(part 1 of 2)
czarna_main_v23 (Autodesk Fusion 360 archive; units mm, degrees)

design "czarna_main" references "sprzeglo_6,35x8mm", "karetka_plecy", "bok_zetki", "SHF_16", "sruba_TR8x8_180mm", "karetka_dol", "uchwyt_nakretki", "Pet_16mm", "Spindle Holder 65mm", "baza_tyl_front", "SMA_16_UU", "Silnik_krokowy_NEMA23", "gora_karetki", "front_zetki", "SA16_500mm", "nowe_plecy_X", "Blat_glowny", "Limit Switch 2", "Nakretka_TR8x8", "stopka", "Water Cooled Spindle Motor 1", "sruba_TR8x8", "bok_x", "baza_bok", "mocowanie_silnika", "KFL_08", "nasadki_boczne", "SME-L16OP"
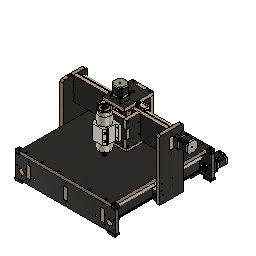
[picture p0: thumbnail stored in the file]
component_insert "Component Insert1"
ground "Ground1"
component_insert "Component Insert2"
component_insert "Component Insert3"
position "Position1"
joint "Assemble2" alignAngle 0 alignOffsetX 0 alignOffsetY 0 alignOffsetZ 0
component_insert "Component Insert4"
joint "Assemble3" alignAngle 0 alignOffsetX 0 alignOffsetY 0 alignOffsetZ 0
component_insert "Component Insert5"
joint "Assemble4" alignAngle 0 alignOffsetX 0 alignOffsetY 0 alignOffsetZ 0
component_insert "Component Insert6"
joint "Assemble5" alignAngle 180 alignOffsetX 0 alignOffsetY 0 alignOffsetZ 0
component_insert "Component Insert7"
joint "Assemble6" alignAngle 0 alignOffsetX 0 alignOffsetY 0 alignOffsetZ 0
component_insert "Component Insert8"
joint "Assemble7" alignAngle -180 alignOffsetX 0 alignOffsetY 0 alignOffsetZ 0
component_insert "Component Insert9"
joint "Assemble8" alignAngle 90 alignOffsetX 0 alignOffsetY 0 alignOffsetZ 0
component_insert "Component Insert10"
joint "Assemble9" alignAngle -90 alignOffsetX 0 alignOffsetY 0 alignOffsetZ 18
component_insert "Component Insert11"
joint "Assemble10" alignAngle 180 alignOffsetX 0 alignOffsetY 0 alignOffsetZ 0
component_insert "Component Insert12"
joint "Assemble11" alignAngle -90 alignOffsetX 0 alignOffsetY 0 alignOffsetZ -28
component_insert "Component Insert13"
joint "Assemble12" alignAngle -90 alignOffsetX 0 alignOffsetY 0 alignOffsetZ 0
component_insert "Component Insert14"
joint "Assemble13" alignAngle -90 alignOffsetX 0 alignOffsetY 9 alignOffsetZ 0
component_insert "Component Insert15"
joint "Assemble14" alignAngle 180 alignOffsetX 0 alignOffsetY 0 alignOffsetZ 0
work_plane "WorkPlane3"
sketch "Sketch3" plane through (280, -360.5, -223.4) normal (-0.2311, 0.9619, -0.146) x axis (-0.9723, -0.2336, 0)
component_insert "Component Insert17"
component_insert "Component Insert18"
joint "Assemble17" alignAngle -90 alignOffsetX 0 alignOffsetY 0 alignOffsetZ 0
component_insert "Component Insert19"
joint "Assemble18" alignAngle 0 alignOffsetX 0 alignOffsetY 0 alignOffsetZ 0
joint "Assemble19" alignAngle 0 alignOffsetX 0 alignOffsetY 0 alignOffsetZ 0
component_insert "Component Insert20"
joint "Assemble20" alignAngle -90 alignOffsetX 0 alignOffsetY 0 alignOffsetZ 0
joint "Assemble21" alignAngle 0 alignOffsetX 0 alignOffsetY 0 alignOffsetZ 0
position "Position4"
position "Position5"
as_built_joint "As-built3"
component_insert "Component Insert21"
joint "Assemble22" alignAngle -180 alignOffsetX 0 alignOffsetY 0 alignOffsetZ 0
component_insert "Component Insert23"
component_insert "Component Insert24"
joint "Assemble25" alignAngle 0 alignOffsetX 0 alignOffsetY 0 alignOffsetZ 0
component_insert "Component Insert25"
joint "Assemble26" alignAngle 0 alignOffsetX 0 alignOffsetY 0 alignOffsetZ 0
component_insert "Component Insert26"
joint "Assemble27" alignAngle 0 alignOffsetX 0 alignOffsetY 0 alignOffsetZ 0
component_insert "Component Insert27"
joint "Assemble28" alignAngle 0 alignOffsetX 0 alignOffsetY 0 alignOffsetZ 0
component_insert "Component Insert29"
component_insert "Component Insert30"
joint "Assemble32" alignAngle -270 alignOffsetX 0 alignOffsetY 0 alignOffsetZ 0
joint "Assemble33" alignAngle -90 alignOffsetX 0 alignOffsetY 0 alignOffsetZ 80
position "Position6"
as_built_joint "As-built4"
joint "Assemble34" alignAngle 0 alignOffsetX 0 alignOffsetY 0 alignOffsetZ 0
position "Position7"
component_insert "Component Insert31"
joint "Assemble35" alignAngle 180 alignOffsetX 0 alignOffsetY 0 alignOffsetZ 0
component_insert "Component Insert32"
joint "Assemble36" alignAngle -90 alignOffsetX 0 alignOffsetY 0 alignOffsetZ 0
component_insert "Component Insert33"
joint "Assemble37" alignAngle 90 alignOffsetX 0 alignOffsetY 0 alignOffsetZ 0
component_insert "Component Insert34"
joint "Assemble38" alignAngle -180 alignOffsetX 0 alignOffsetY 0 alignOffsetZ 0
component_insert "Component Insert35"
joint "Assemble39" alignAngle 0 alignOffsetX 0 alignOffsetY 0 alignOffsetZ 0
component_insert "Component Insert36"
joint "Assemble40" alignAngle 90 alignOffsetX 0 alignOffsetY 0 alignOffsetZ 0
component_insert "Component Insert37"
joint "Assemble41" alignAngle 90 alignOffsetX 0 alignOffsetY 0 alignOffsetZ -24
component_insert "Component Insert39"
joint "Assemble42" alignAngle 180 alignOffsetX 0 alignOffsetY 0 alignOffsetZ 0
component_insert "Component Insert40"
joint "Assemble43" alignAngle 0 alignOffsetX 0 alignOffsetY 0 alignOffsetZ 0
component_insert "Component Insert41"
joint "Assemble44" alignAngle 0 alignOffsetX 0 alignOffsetY 0 alignOffsetZ 0
component_insert "Component Insert42"
joint "Assemble45" alignAngle 180 alignOffsetX 0 alignOffsetY 0 alignOffsetZ 0
component_insert "Component Insert43"
joint "Assemble46" alignAngle 180 alignOffsetX 0 alignOffsetY 0 alignOffsetZ 0
component_insert "Component Insert44"
joint "Assemble47" alignAngle 0 alignOffsetX 0 alignOffsetY 0 alignOffsetZ 0
component_insert "Component Insert45"
joint "Assemble48" alignAngle 180 alignOffsetX 0 alignOffsetY 0 alignOffsetZ 0
component_insert "Component Insert46"
joint "Assemble49" alignAngle 0 alignOffsetX 0 alignOffsetY 0 alignOffsetZ 0
component_insert "Component Insert47"
joint "Assemble50" alignAngle 0 alignOffsetX 0 alignOffsetY 0 alignOffsetZ 0
component_insert "Component Insert48"
joint "Assemble51" alignAngle -180 alignOffsetX 0 alignOffsetY 0 alignOffsetZ 0
component_insert "Component Insert49"
joint "Assemble52" alignAngle 180 alignOffsetX 0 alignOffsetY 0 alignOffsetZ 0
component_insert "Component Insert50"
joint "Assemble53" alignAngle 90 alignOffsetX 0 alignOffsetY 0 alignOffsetZ 0
component_insert "Component Insert51"
joint "Assemble54" alignAngle -90 alignOffsetX 0 alignOffsetY 0 alignOffsetZ 0
component_insert "Component Insert52"
joint "Assemble55" alignAngle 0 alignOffsetX 0 alignOffsetY 0 alignOffsetZ -47
component_insert "Component Insert53"
joint "Assemble56" alignAngle -90 alignOffsetX 0 alignOffsetY 0 alignOffsetZ -26
position "Position8"
component_insert "Component Insert54"
joint "Assemble57" alignAngle -90 alignOffsetX 0 alignOffsetY 0 alignOffsetZ 0
component_insert "Component Insert55"
joint "Assemble58" alignAngle 0 alignOffsetX 0 alignOffsetY 0 alignOffsetZ 0
position "Position9"
as_built_joint "As-built5"
component_insert "Component Insert56"
joint "Assemble59" alignAngle 0 alignOffsetX 0 alignOffsetY 0 alignOffsetZ 0
component_insert "Component Insert57"
joint "Assemble60" alignAngle 180 alignOffsetX 0 alignOffsetY 0 alignOffsetZ 0
position "Position10"
sketch "Sketch7" plane through (280, -360.5, -223.4) normal (-0.2311, 0.9619, -0.146) x axis (-0.9723, -0.2336, 0)
component_insert "Component Insert58"
joint "Assemble62" alignAngle 180 alignOffsetX 0 alignOffsetY 0 alignOffsetZ 0
component_insert "Component Insert59"
joint "Assemble63" alignAngle 180 alignOffsetX 0 alignOffsetY 0 alignOffsetZ 0
component_insert "Component Insert60"
component_insert "Component Insert61"
component_insert "Component Insert62"
component_insert "Component Insert63"
component_insert "Component Insert64"
joint "Assemble66" alignAngle 90 alignOffsetX 0 alignOffsetY 0 alignOffsetZ 0
component_insert "Component Insert65"
joint "Assemble67" alignAngle 90 alignOffsetX 0 alignOffsetY 0 alignOffsetZ 0
component_insert "Component Insert66"
component_insert "Component Insert67"
joint "Assemble70" alignAngle -90 alignOffsetX 0 alignOffsetY 0 alignOffsetZ 0
component_insert "Component Insert68"
joint "Assemble71" alignAngle 90 alignOffsetX 0 alignOffsetY 0 alignOffsetZ 0
component_insert "Component Insert69"
joint "Assemble72" alignAngle -90 alignOffsetX 0 alignOffsetY 0 alignOffsetZ 0
component_insert "Component Insert70"
joint "Assemble73" alignAngle 90 alignOffsetX 0 alignOffsetY 0 alignOffsetZ 0
position "Position11"
as_built_joint "As-built6"
joint "Assemble75" alignAngle 90 alignOffsetX 0 alignOffsetY 0 alignOffsetZ 0
component_insert "Component Insert71"
joint "Assemble76" alignAngle 0 alignOffsetX 0 alignOffsetY 0 alignOffsetZ 0
component_insert "Component Insert72"
joint "Assemble77" alignAngle -180 alignOffsetX 0 alignOffsetY 0 alignOffsetZ 0
component_insert "Component Insert73"
joint "Assemble78" alignAngle 0 alignOffsetX 0 alignOffsetY 0 alignOffsetZ 0
component_insert "Component Insert74"
joint "Assemble79" alignAngle 180 alignOffsetX 0 alignOffsetY 0 alignOffsetZ -10
joint "Assemble80" alignAngle -90 alignOffsetX 0 alignOffsetY 0 alignOffsetZ 0
position "Position12"
position "Position13"
work_plane "WorkPlane5"
sketch "Sketch12" plane through (280, -360.5, -220.4) normal (-0.2194, 0.964, -0.1502) x axis (-0.9751, -0.2219, 0)
component_insert "Component Insert75"
joint "Assemble81" alignAngle 0 alignOffsetX -70 alignOffsetY 9 alignOffsetZ 0
component_insert "Component Insert76"
joint "Assemble82" alignAngle -270 alignOffsetX 1 alignOffsetY -21 alignOffsetZ 0
component_insert "Component Insert77"
joint "Assemble83" alignAngle 0 alignOffsetX 0 alignOffsetY 0 alignOffsetZ 0
component_insert "Component Insert78"
joint "Assemble84" alignAngle 0 alignOffsetX 0 alignOffsetY 0 alignOffsetZ 0
joint "Złóż89" alignAngle 180 alignOffsetX 0 alignOffsetY 0 alignOffsetZ 0
joint "Złóż90" alignAngle 0 alignOffsetX 0 alignOffsetY 0 alignOffsetZ 0
component_insert "Wstawianie komponentu79"
joint "Złóż91" alignAngle 180 alignOffsetX 0 alignOffsetY 0 alignOffsetZ 0
component_insert "Wstawianie komponentu80"
joint "Złóż92" alignAngle 0 alignOffsetX 0 alignOffsetY 0 alignOffsetZ -10
position "Pozycja"
step "Kontekst"

design "sruba_TR8x8"
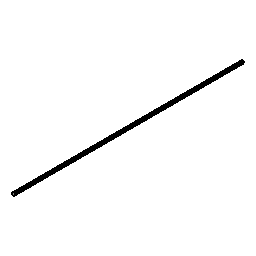
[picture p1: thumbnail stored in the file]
base_feature "Base Feature"
extrude "Extrude1" new body sketch "Reconstructed-Sketch1" blind 540
thread "Thread1"
extrude "Extrude2" cut sketch "Reconstructed-Sketch1" blind 50
extrude "Extrude3" cut of existing geometry blind -50

design "sruba_TR8x8_180mm"
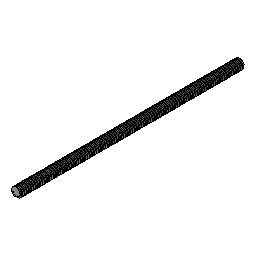
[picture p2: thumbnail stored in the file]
base_feature "Base Feature"
extrude "Extrude1" new body sketch "Reconstructed-Sketch1" blind 180
thread "Thread1"
extrude "Extrude2" cut sketch "Reconstructed-Sketch1" blind 50
extrude "Extrude3" cut of existing geometry blind -50

design "Blat_glowny"
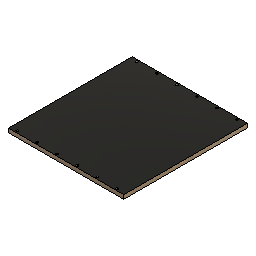
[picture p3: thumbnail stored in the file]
derived_context "DerivedContext1"
sketch "Sketch1" plane through (0, 0, -80.4) normal (0, 0, 1) x axis (-1, 0, 0)
  line L1 (-249, -175.5) -> (-249, 360.5)
  line L2 (249, -175.5) -> (-249, -175.5)
  line L3 (249, 360.5) -> (249, -175.5)
  line L4 (-249, 360.5) -> (249, 360.5)
  line L5 (-249, 360.5) -> (249, 360.5)
  line L6 (-249, -175.5) -> (-249, 360.5)
  line L7 (249, -175.5) -> (-249, -175.5)
  line L8 (249, 360.5) -> (249, -175.5)
  point P3 (-249, -175.5)
  point P8 (-249, -175.5)
  point P5 (249, 360.5)
  point P6 (249, 360.5)
  horizontal L5
  vertical L6
  horizontal L7
  vertical L8
  coincident P3 P8
  coincident P5 P6
extrude "Extrude1" new body sketch "Sketch1" against normal blind 18
sketch "Sketch2" plane through (0, 0, -80.4) normal (0, 0, 1) x axis (-1, 0, 0)
  line L1 (249, 360.5) -> (249, -175.5)
  line L2 (-249, 360.5) -> (249, 360.5)
  line L3 (-249, -175.5) -> (-249, 360.5)
  line L4 (249, -175.5) -> (-249, -175.5)
  circle C1 centre (229, 351.5) radius 2.5
  point P6 (229, 351.5)
  dimension "d3" diameter C1 = 5
  dimension "d4" distance L1 P6 = 20
  dimension "d5" distance L2 P6 = 9
extrude "Extrude2" cut sketch "Sketch2" profile of C1 against normal blind 18
chamfer "Chamfer1" distance 2.5 distance 3
rectangular_pattern "R-Pattern1" uSpaceDistance 450 vSpaceDistance 0
extrude "Extrude3" add of existing geometry blind 10
extrude "Extrude4" add of existing geometry blind 10
extrude "Extrude5" add of existing geometry blind 20
work_plane "WorkPlane1"
mirror "Mirror2" mirrorStitchTolerance 0.1
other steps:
derived_base_feature "Derived Base Feature1" bodies "Body1"
derived_base_feature "Derived Base Feature2"
named bodies: "Body1"

design "uchwyt_nakretki"
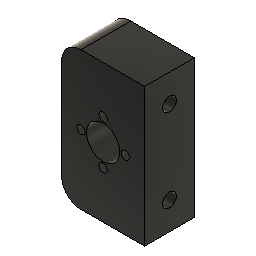
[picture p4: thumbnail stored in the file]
derived_context "DerivedContext1"
sketch "Sketch1" plane through (252, 0, 0) normal (-1, 0, 0) x axis (0, -1, 0)
  line L1 (0, -205) -> (0, 130)
  line L2 (135, -205) -> (0, -205)
  line L3 (135, 130) -> (135, -205)
  line L4 (0, 130) -> (135, 130)
  line L5 (117, -205) -> (135, -205)
  line L6 (117, -155) -> (117, -205)
  line L7 (135, -155) -> (117, -155)
  line L8 (135, -205) -> (135, -155)
  circle C1 centre (122.5, -139.4) radius 2.067
  circle C2 centre (62.5, -107.4) radius 2.067
  circle C3 centre (122.5, -107.4) radius 2.067
  circle C4 centre (62.5, -139.4) radius 2.067
  circle C5 centre (25, 55) radius 14
  point P9 (135, -205)
  point P11 (135, -205)
  point P12 (117, -205)
  point P14 (135, -155)
  horizontal L5
  vertical L6
  horizontal L7
  vertical L8
  coincident P9 P11
  dimension "d1" distance P11 P12 = 18
  dimension "d2" distance P11 P14 = 50
extrude "Extrude1" new body sketch "Sketch1" profile of L2 L3 L5 L6 L7 L8 along normal blind 30
sketch "Sketch2" plane through (0, -135, 0) normal (0, -1, 0) x axis (1, 0, 0)
  line L1 (252, -155) -> (252, -205)
  line L2 (222, -155) -> (252, -155)
  line L3 (222, -205) -> (222, -155)
  line L4 (252, -205) -> (222, -205)
  circle C1 centre (245, -178.4) radius 1.85
  circle C2 centre (229, -178.4) radius 1.85
  circle C3 centre (237, -178.4) radius 10.8
  circle C4 centre (237, -178.4) radius 5.35
  circle C5 centre (237, -170.4) radius 1.85
  circle C6 centre (237, -186.4) radius 1.85
  circle C7 centre (237, -170.4) radius 1.5
  circle C8 centre (237, -178.4) radius 6
  circle C9 centre (229, -178.4) radius 1.5
  circle C10 centre (237, -186.4) radius 1.5
  circle C11 centre (245, -178.4) radius 1.5
  concentric C5 C7
  concentric C3 C8
  dimension "d19" diameter C7 = 3
  dimension "d20" diameter C8 = 12
  dimension "d22" C-Pattern1-Angle = 360
extrude "Extrude2" cut sketch "Sketch2" profile of C4 C7 C8 C9 C10 C11 against normal blind 18
sketch "Sketch4" plane through (222, 0, 0) normal (-1, 0, 0) x axis (0, -1, 0)
  line L1 (117, -155) -> (135, -155)
  line L2 (117, -205) -> (117, -155)
  line L3 (135, -205) -> (117, -205)
  line L4 (135, -155) -> (135, -205)
  line L5 (135, -205) -> (135, 130)
  line L6 (135, -155) -> (117, -155)
  circle C1 centre (126, -195) radius 2.5
  circle C2 centre (126, -165) radius 2.5
  point P7 (126, -165)
  point P6 (126, -195)
  dimension "d7" diameter C1 = 5
  dimension "d8" diameter C2 = 5
  dimension "d13" distance P7 L5 = 9
  dimension "d14" distance L3 P6 = 10
  dimension "d15" distance P6 L5 = 9
  dimension "d16" distance P7 L6 = 10
extrude "Extrude3" cut sketch "Sketch4" profile of C1 C2 against normal blind 32
fillet "Fillet1" radius 7
sketch "Sketch5" plane through (222, 0, 0) normal (-1, 0, 0) x axis (0, -1, 0)
  line L1 (135, -198) -> (117, -198)
  line L2 (135, -162) -> (135, -198)
  line L3 (117, -162) -> (135, -162)
  line L4 (117, -198) -> (117, -162)
  line L5 (121.2369, -162.25) -> (126, -159.5)
  line L6 (121.2369, -167.75) -> (121.2369, -162.25)
  line L7 (126, -170.5) -> (121.2369, -167.75)
  line L8 (130.7631, -167.75) -> (126, -170.5)
  line L9 (130.7631, -162.25) -> (130.7631, -167.75)
  line L10 (126, -159.5) -> (130.7631, -162.25)
  line L11 (121.2369, -192.25) -> (126, -189.5)
  line L12 (121.2369, -197.75) -> (121.2369, -192.25)
  line L13 (126, -200.5) -> (121.2369, -197.75)
  line L14 (130.7631, -197.75) -> (126, -200.5)
  line L15 (130.7631, -192.25) -> (130.7631, -197.75)
  line L16 (126, -189.5) -> (130.7631, -192.25)
  circle C1 centre (126, -195) radius 2.5
  circle C2 centre (126, -165) radius 2.5
  point P3 (126, -165)
  point P14 (126, -165)
  point P2 (126, -195)
  point P21 (126, -195)
  point P8 (126, -159.5)
  point P15 (126, -189.5)
  coincident P3 P14
  coincident P2 P21
  dimension "d23" distance P8 P14 = 5.5
  dimension "d24" distance P15 P21 = 5.5
extrude "Extrude5" cut sketch "Sketch5" profile of C1 C2 L1 L3 L5 L6 L7 L8 L9 L10 L11 L12 L13 L14 L15 L16 against normal blind 6
move_face "MoveFace2" TranslateX 0 TranslateY 0 TranslateZ -1.6
extrude "Extrude4" cut of existing geometry blind -5
sketch "Sketch3" plane through (0, -135, 0) normal (0, -1, 0) x axis (1, 0, 0)
  line L1 (270, 130) -> (270, -205)
  line L2 (252, 130) -> (270, 130)
  line L3 (252, -205) -> (252, 130)
  line L4 (270, -205) -> (252, -205)
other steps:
derived_base_feature "Derived Base Feature1" bodies "Body1"
derived_base_feature "Derived Base Feature2" bodies "Body1 (1)"
named bodies: "Body1", "Body1 (1)"

design "Spindle Holder 65mm"
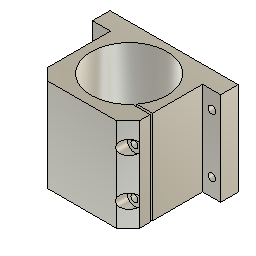
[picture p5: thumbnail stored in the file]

design "baza_bok"
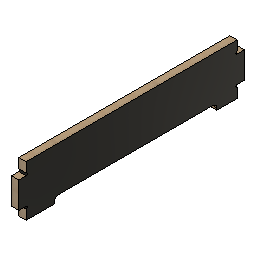
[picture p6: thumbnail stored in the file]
derived_context "$ 169cf05e-f77e-4d37-a624-d0ff3fc9afd0쑒썌㵎$ a4974d71-8db2-4fde-91a5-83f0541c0199́   Ā烧䴪뭹␀ 䔀㌰㠷䔴ⵄ䔵㤱㐭ㅅⴴ㥂㉆㌭あ〷㜱㄰䌸D  czarnula_main v21     Ā¶          뼁    Ā Āఙ   ⩰⫫祍»$ ㍄㌹〷㠲䌭〲ⵃ"
sketch "Sketch1" plane through (207, 0, 0) normal (1, 0, 0) x axis (0, 1, 0)
  line L1 (157.5, -223.4) -> (-342.5, -223.4)
  line L2 (157.5, -98.4) -> (157.5, -223.4)
  line L3 (-342.5, -98.4) -> (157.5, -98.4)
  line L4 (-342.5, -223.4) -> (-342.5, -98.4)
  line L5 (157.5, -98.4) -> (-342.5, -98.4)
  line L6 (157.5, -223.4) -> (157.5, -98.4)
  line L7 (-342.5, -223.4) -> (157.5, -223.4)
  line L8 (-342.5, -98.4) -> (-342.5, -223.4)
  line L9 (139.5, -128.4) -> (175.5, -128.4)
  line L10 (139.5, -193.4) -> (139.5, -128.4)
  line L11 (175.5, -193.4) -> (139.5, -193.4)
  line L12 (175.5, -128.4) -> (175.5, -193.4)
  line L13 (139.5, -193.4) -> (175.5, -128.4)
  line L14 (175.5, -193.4) -> (139.5, -128.4)
  line L15 (-324.5, -193.4) -> (-360.5, -193.4)
  line L16 (-324.5, -128.4) -> (-324.5, -193.4)
  line L17 (-360.5, -128.4) -> (-324.5, -128.4)
  line L18 (-360.5, -193.4) -> (-360.5, -128.4)
  line L19 (-324.5, -128.4) -> (-360.5, -193.4)
  line L20 (-360.5, -128.4) -> (-324.5, -193.4)
  line L21 (97.5, -208.4) -> (-282.5, -208.4)
  line L22 (107.5, -238.4) -> (107.5, -218.4)
  line L23 (-292.5, -238.4) -> (107.5, -238.4)
  line L24 (-292.5, -218.4) -> (-292.5, -238.4)
  line L25 (107.5, -238.4) -> (-292.5, -208.4)
  line L26 (-292.5, -238.4) -> (107.5, -208.4)
  arc A1 centre (-282.5, -218.4) radius 10 clockwise from (-292.5, -218.4) to (-282.5, -208.4)
  arc A2 centre (97.5, -218.4) radius 10 clockwise from (97.5, -208.4) to (107.5, -218.4)
  point P3 (157.5, -223.4)
  point P8 (157.5, -223.4)
  point P5 (-342.5, -98.4)
  point P6 (-342.5, -98.4)
  point P14 (157.5, -160.9)
  point P19 (-342.5, -160.9)
  point P24 (-92.5, -223.4)
  point P20 (-292.5, -208.4)
  point P21 (107.5, -208.4)
  point P12 (139.5, -193.4)
  point P13 (175.5, -193.4)
  point P11 (139.5, -128.4)
  point P17 (-324.5, -128.4)
  point P18 (-360.5, -128.4)
  point P16 (-324.5, -193.4)
  point P22 (107.5, -238.4)
  point P23 (-292.5, -238.4)
  horizontal L5
  vertical L6
  horizontal L7
  vertical L8
  coincident P3 P8
  coincident P5 P6
  horizontal L9
  perpendicular L9 L10
  parallel L9 L11
  parallel L10 L12
  coincident L13 P14
  coincident L14 P14
  midpoint L2 P14
  horizontal L15
  perpendicular L15 L16
  parallel L15 L17
  parallel L16 L18
  coincident L19 P19
  coincident L20 P19
  midpoint L8 P19
  horizontal L21
  perpendicular L21 L22
  parallel L21 L23
  parallel L22 L24
  coincident L25 P24
  coincident L26 P24
  midpoint L7 P24
  coincident P20 L21
  coincident P20 L24
  tangent L21 A1
  tangent L24 A1
  coincident P21 L22
  coincident P21 L21
  tangent L22 A2
  tangent L21 A2
  equal A1 A2
  dimension "d3" distance P12 P13 = 36
  dimension "d4" distance P11 P12 = 65
  dimension "d5" distance P17 P18 = 36
  dimension "d6" distance P16 P17 = 65
  dimension "d7" distance P22 P23 = 400
  dimension "d8" distance P21 P22 = 30
  dimension "d9" radius A1 = 10
extrude "Extrude1" new body sketch "Sketch1" profile of L1 L2 L3 L4 L5 L6 L7 L8 L9 L10 L11 L12 L15 L16 L17 L18 L21 L22 L24 A1 A2 against normal blind 18
sketch "Sketch2" plane through (0, -342.5, 0) normal (0, -1, 0) x axis (1, 0, 0)
  line L1 (207, -98.4) -> (207, -128.4)
  line L2 (189, -98.4) -> (207, -98.4)
  line L3 (189, -128.4) -> (189, -98.4)
  line L4 (207, -223.4) -> (189, -223.4)
  line L5 (207, -128.4) -> (189, -128.4)
  line L6 (207, -193.4) -> (207, -223.4)
  line L7 (189, -193.4) -> (207, -193.4)
  line L8 (189, -223.4) -> (189, -193.4)
extrude "Extrude2" add of existing geometry blind 20
extrude "Extrude3" add of existing geometry blind 20
sketch "Sketch3" plane through (207, 0, 0) normal (1, 0, 0) x axis (0, 1, 0)
  line L1 (175.5, -193.4) -> (157.5, -193.4)
  line L2 (175.5, -128.4) -> (175.5, -193.4)
  line L3 (157.5, -128.4) -> (175.5, -128.4)
  line L4 (157.5, -98.4) -> (157.5, -128.4)
  line L5 (-362.5, -98.4) -> (157.5, -98.4)
  line L6 (-362.5, -128.4) -> (-362.5, -98.4)
  line L7 (-380.5, -128.4) -> (-362.5, -128.4)
  line L8 (-380.5, -193.4) -> (-380.5, -128.4)
  line L9 (-362.5, -193.4) -> (-380.5, -193.4)
  line L10 (-362.5, -223.4) -> (-362.5, -193.4)
  line L11 (-292.5, -223.4) -> (-362.5, -223.4)
  line L12 (-292.5, -218.4) -> (-292.5, -223.4)
  line L13 (97.5, -208.4) -> (-282.5, -208.4)
  line L14 (107.5, -223.4) -> (107.5, -218.4)
  line L15 (157.5, -223.4) -> (107.5, -223.4)
  line L16 (157.5, -193.4) -> (157.5, -223.4)
  line L17 (175.5, -160.9) -> (-380.5, -160.9)
  line L18 (-102.5, -208.4) -> (-102.5, -98.4)
  arc A1 centre (-282.5, -218.4) radius 10 clockwise from (-292.5, -218.4) to (-282.5, -208.4)
  arc A2 centre (97.5, -218.4) radius 10 clockwise from (97.5, -208.4) to (107.5, -218.4)
  circle C1 centre (-362.5, -125.4) radius 3
  circle C2 centre (-362.5, -196.4) radius 3
  circle C3 centre (157.5, -125.4) radius 3
  circle C4 centre (157.5, -196.4) radius 3
  point P22 (-380.5, -160.9)
  point P23 (175.5, -160.9)
  point P24 (-102.5, -98.4)
  point P25 (-102.5, -208.4)
  point P26 (-362.5, -125.4)
  midpoint L8 P22
  midpoint L2 P23
  midpoint L5 P24
  coincident L13 P25
  perpendicular L13 L18
  coincident L6 P26
  symmetric L17 C1 C2
  symmetric L18 C1 C3
  symmetric L18 C2 C4
  dimension "d15" diameter C1 = 6
  dimension "d16" distance L7 P26 = 3
extrude "Extrude4" cut sketch "Sketch3" profile of L4 L6 L10 L16 C1 C2 C3 C4 against normal blind 40
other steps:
derived_base_feature "Derived Base Feature" bodies "Body1"
named bodies: "Body1"

design "Pet_16mm"
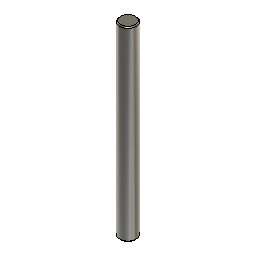
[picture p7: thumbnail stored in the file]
derived_context "DerivedContext1"
sketch "Sketch1" plane through (0, 0, -6) normal (0, 0, 1) x axis (-1, 0, 0)
  line L1 (75, 5) -> (-45, 5)
  line L2 (75, 125) -> (75, 5)
  line L3 (-45, 125) -> (75, 125)
  line L4 (-45, 5) -> (-45, 125)
  circle C1 centre (60, 100) radius 8
  dimension "d1" diameter C1 = 16
extrude "Extrude1" new body sketch "Sketch1" profile of C1 along normal blind 180
chamfer "Chamfer1" distance 1
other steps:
derived_base_feature "Derived Base Feature" bodies "Body1"
named bodies: "Body1"

design "KFL_08"
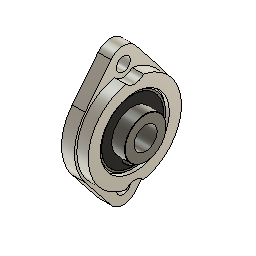
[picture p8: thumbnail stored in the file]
base_feature "Base Feature1"
base_feature "Base Feature1"
as_built_joint "As-built4"
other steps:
create_component "CreateComponent1"
create_component "CreateComponent2"

design "bok_x"
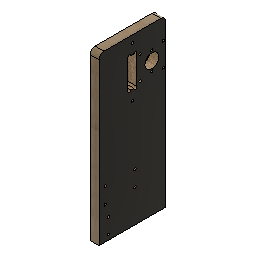
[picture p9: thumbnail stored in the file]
derived_context "$ 8c4a07d2-4c8d-4ca5-ad19-81678df19577酠଼ۘ$ a4974d71-8db2-4fde-91a5-83f0541c0199́   Ā⛱ă붫␀ 䔀㌰㠷䔴ⵄ䔵㤱㐭ㅅⴴ㥂㉆㌭あ〷㜱㄰䌸D  czarnula_main v69   Ȁ ĀЊ    ᐁ    Ā¶          뼁    Ā ĀƔ   椁̦"
derived_context "DerivedContext2"
derived_context "DerivedContext3"
derived_context "DerivedContext4"
sketch "Sketch1" plane through (0, 0, -55) normal (0, -1, 0) x axis (1, 0, 0)
  line L1 (-270, 185) -> (270, 185)
  line L2 (-270, 35) -> (-270, 185)
  line L3 (270, 35) -> (-270, 35)
  line L4 (270, 185) -> (270, 35)
  line L5 (252, 185) -> (270, 185)
  line L6 (252, 35) -> (252, 185)
  line L7 (270, 35) -> (252, 35)
  line L8 (270, 185) -> (270, 35)
  point P2 (270, 185)
  point P6 (270, 185)
  point P7 (252, 185)
  point P9 (270, 35)
  horizontal L5
  vertical L6
  horizontal L7
  vertical L8
  coincident P2 P6
  dimension "d1" distance P6 P7 = 18
  dimension "d2" distance P6 P9 = 150
extrude "Extrude1" new body sketch "Sketch1" profile of L1 L3 L4 L5 L6 L7 L8 along normal blind 135
extrude "Extrude2" add of existing geometry blind 185
sketch "Sketch2" plane through (270, 0, 0) normal (1, 0, 0) x axis (0, 1, 0)
  line L1 (0, 130) -> (0, -205)
  line L2 (-135, 130) -> (0, 130)
  line L3 (-135, -205) -> (-135, 130)
  line L4 (0, -205) -> (-135, -205)
  line L5 (-125, -155) -> (-107, -155)
  line L6 (-125, -205) -> (-125, -155)
  line L7 (-107, -205) -> (-125, -205)
  line L8 (-107, -155) -> (-107, -205)
  line L9 (-50.9, -134.29) -> (-50.9, -145)
  line L10 (-134.1, -134.29) -> (-50.9, -134.29)
  line L11 (-134.1, -145) -> (-134.1, -134.29)
  line L12 (-50.9, -145) -> (-134.1, -145)
  line L13 (-50.9, -101.8) -> (-50.9, -112.51)
  line L14 (-134.1, -101.8) -> (-50.9, -101.8)
  line L15 (-134.1, -112.51) -> (-134.1, -101.8)
  line L16 (-50.9, -112.51) -> (-134.1, -112.51)
  circle C1 centre (-116, -195) radius 2.5
  circle C2 centre (-116, -165) radius 2.5
  circle C3 centre (-62.5, -139.4) radius 2.5
  circle C4 centre (-122.5, -139.4) radius 2.5
  circle C5 centre (-62.5, -107.4) radius 2.5
  circle C6 centre (-122.5, -107.4) radius 2.5
extrude "Extrude3" cut sketch "Sketch2" profile of C1 C2 C3 C4 C5 C6 against normal blind 18
sketch "Sketch4" plane through (270, 0, 0) normal (1, 0, 0) x axis (0, 1, 0)
  line L1 (0, 130) -> (0, -205)
  line L2 (-135, 130) -> (0, 130)
  line L3 (-135, -205) -> (-135, 130)
  line L4 (0, -205) -> (-135, -205)
  line L5 (-26.0251, 104.4302) -> (-14.6716, 93.0767)
  line L6 (-66.3302, 69.0749) -> (-30.9749, 104.4302)
  line L7 (-30.9749, 28.7698) -> (-66.3302, 64.1251)
  line L8 (-14.6716, 40.1233) -> (-26.0251, 28.7698)
  line L9 (-13.5, 43.3621) -> (-13.5, 42.9518)
  line L10 (-13.5, 90.2482) -> (-13.5, 89.8379)
  circle C1 centre (-116, -165) radius 2.5
  circle C2 centre (-62.5, -139.4) radius 2.5
  circle C3 centre (-122.5, -139.4) radius 2.5
  circle C4 centre (-122.5, -107.4) radius 2.5
  circle C5 centre (-62.5, -107.4) radius 2.5
  circle C6 centre (-116, -195) radius 2.5
  arc A1 centre (-17.5, 90.2482) radius 4 clockwise from (-14.6716, 93.0767) to (-13.5, 90.2482)
  arc A2 centre (-28.5, 101.9553) radius 3.5 clockwise from (-30.9749, 104.4302) to (-26.0251, 104.4302)
  arc A3 centre (-63.8553, 66.6) radius 3.5 clockwise from (-66.3302, 64.1251) to (-66.3302, 69.0749)
  arc A4 centre (-28.5, 31.2447) radius 3.5 clockwise from (-26.0251, 28.7698) to (-30.9749, 28.7698)
  arc A5 centre (-17.5, 42.9518) radius 4 clockwise from (-13.5, 42.9518) to (-14.6716, 40.1233)
  arc A6 centre (-18, 43.3621) radius 4.5 clockwise from (-19.8529, 47.4629) to (-13.5, 43.3621)
  arc A7 centre (-28.5, 66.6) radius 21 clockwise from (-19.8529, 47.4629) to (-19.8529, 85.7371)
  arc A8 centre (-18, 89.8379) radius 4.5 clockwise from (-13.5, 89.8379) to (-19.8529, 85.7371)
  circle C7 centre (-28.5, 33.1934) radius 2.54
  circle C8 centre (-28.5, 100.0066) radius 2.54
  circle C9 centre (-61.9066, 66.6) radius 2.54
  circle C10 centre (-28.5, 66.6) radius 14
  concentric A7 C10
  dimension "d22" diameter C10 = 28
extrude "Extrude6" cut sketch "Sketch4" profile of C10 against normal blind 20
sketch "Sketch5" plane through (270, 0, 0) normal (1, 0, 0) x axis (0, 1, 0)
  line L1 (0, 130) -> (0, -205)
  line L2 (-135, 130) -> (0, 130)
  line L3 (-135, -205) -> (-135, 130)
  line L4 (0, -205) -> (-135, -205)
  line L5 (-0.9156, 41.2) -> (-0.9156, 92)
  line L6 (-53.9, 39.0156) -> (-3.1, 39.0156)
  line L7 (-56.0844, 92) -> (-56.0844, 41.2)
  line L8 (-3.1, 94.1844) -> (-53.9, 94.1844)
  circle C1 centre (-28.5, 66.6) radius 14
  circle C2 centre (-116, -165) radius 2.5
  circle C3 centre (-62.5, -139.4) radius 2.5
  circle C4 centre (-122.5, -139.4) radius 2.5
  circle C5 centre (-122.5, -107.4) radius 2.5
  circle C6 centre (-62.5, -107.4) radius 2.5
  circle C7 centre (-116, -195) radius 2.5
  arc A1 centre (-3.1, 92) radius 2.1844 clockwise from (-3.1, 94.1844) to (-0.9156, 92)
  arc A2 centre (-3.1, 41.2) radius 2.1844 clockwise from (-0.9156, 41.2) to (-3.1, 39.0156)
  arc A3 centre (-53.9, 41.2) radius 2.1844 clockwise from (-53.9, 39.0156) to (-56.0844, 41.2)
  arc A4 centre (-53.9, 92) radius 2.1844 clockwise from (-56.0844, 92) to (-53.9, 94.1844)
  circle C8 centre (-28.5, 66.6) radius 20.32
  circle C9 centre (-4.878, 90.222) radius 2.54
  circle C10 centre (-4.878, 42.978) radius 2.54
  circle C11 centre (-52.122, 42.978) radius 2.54
  circle C12 centre (-52.122, 90.222) radius 2.54
extrude "Extrude7" cut sketch "Sketch5" profile of C9 C10 C11 C12 against normal blind 18
sketch "Sketch6" plane through (252, 0, 0) normal (-1, 0, 0) x axis (0, -1, 0)
  line L1 (0, -205) -> (0, 130)
  line L2 (135, -205) -> (0, -205)
  line L3 (135, 130) -> (135, -205)
  line L4 (0, 130) -> (135, 130)
  circle C1 centre (4.878, 90.222) radius 2.54
  circle C2 centre (4.878, 42.978) radius 2.54
  circle C3 centre (52.122, 90.222) radius 2.54
  circle C4 centre (52.122, 42.978) radius 2.54
  circle C5 centre (28.5, 66.6) radius 14
  circle C6 centre (116, -165) radius 2.5
  circle C7 centre (62.5, -139.4) radius 2.5
  circle C8 centre (122.5, -139.4) radius 2.5
  circle C9 centre (122.5, -107.4) radius 2.5
  circle C10 centre (62.5, -107.4) radius 2.5
  circle C11 centre (116, -195) radius 2.5
  circle C12 centre (28.5, 85.1) radius 2.4
  circle C13 centre (28.5, 48.1) radius 2.4
  circle C14 centre (28.5, 48.1) radius 2.4
extrude "Extrude8" cut sketch "Sketch6" profile of C12 C13 C14 against normal blind 18
move_face "MoveFace1" TranslateX 0 TranslateY 0 TranslateZ -1.6
sketch "Sketch7" plane through (270, 0, 0) normal (1, 0, 0) x axis (0, 1, 0)
  line L1 (0, 130) -> (0, -205)
  line L2 (-135, 130) -> (0, 130)
  line L3 (-135, -205) -> (-135, 130)
  line L4 (0, -205) -> (-135, -205)
  line L5 (-58.5, 95) -> (-76.5, 95)
  line L6 (-58.5, 35) -> (-58.5, 95)
  line L7 (-76.5, 35) -> (-58.5, 35)
  line L8 (-76.5, 95) -> (-76.5, 35)
  circle C1 centre (-28.5, 83.5) radius 2.4
  circle C2 centre (-28.5, 46.5) radius 2.4
  circle C3 centre (-4.878, 88.622) radius 2.54
  circle C4 centre (-4.878, 41.378) radius 2.54
  circle C5 centre (-52.122, 88.622) radius 2.54
  circle C6 centre (-52.122, 41.378) radius 2.54
  circle C7 centre (-28.5, 65) radius 14
  circle C8 centre (-116, -165) radius 2.5
  circle C9 centre (-62.5, -139.4) radius 2.5
  circle C10 centre (-122.5, -139.4) radius 2.5
  circle C11 centre (-122.5, -107.4) radius 2.5
  circle C12 centre (-62.5, -107.4) radius 2.5
  circle C13 centre (-116, -195) radius 2.5
  circle C14 centre (-67.5, 115) radius 2.5
  circle C15 centre (-67.5, 15) radius 2.5
  circle C16 centre (-73.5, 95) radius 3
  circle C17 centre (-61.5, 95) radius 3
  circle C18 centre (-73.5, 35) radius 3
  circle C19 centre (-61.5, 35) radius 3
  point P25 (-73.5, 95)
  point P26 (-61.5, 95)
  point P27 (-73.5, 35)
  point P28 (-61.5, 35)
  point P21 (-58.5, 35)
  point P22 (-76.5, 35)
  point P19 (-76.5, 95)
  point P24 (-67.5, 15)
  point P20 (-58.5, 95)
  point P23 (-67.5, 115)
  horizontal L5
  vertical L6
  horizontal L7
  vertical L8
  coincident L5 P25
  coincident L5 P26
  coincident L7 P27
  coincident L7 P28
  dimension "d32" distance P21 P22 = 18
  dimension "d33" distance L1 L6 = 58.5
  dimension "d34" distance P19 P22 = 60
  dimension "d35" distance L2 L5 = 35
  dimension "d36" diameter C15 = 5
  dimension "d37" distance L6 P24 = 9
  dimension "d38" diameter C14 = 5
  dimension "d39" distance P20 P23 = 9
  dimension "d40" distance L5 P23 = 20
  dimension "d41" distance L7 P24 = 20
  dimension "d44" diameter C16 = 6
  dimension "d45" diameter C17 = 6
  dimension "d46" distance L8 P25 = 3
  dimension "d47" distance L6 P26 = 3
  dimension "d48" diameter C18 = 6
  dimension "d49" diameter C19 = 6
  dimension "d50" distance L8 P27 = 3
  dimension "d51" distance L6 P28 = 3
extrude "Extrude9" cut sketch "Sketch7" profile of L5 L6 L7 L8 C14 C15 C16 C17 C18 C19 against normal blind 20
fillet "Fillet1" radius 10
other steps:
derived_base_feature "Derived Base Feature1" bodies "Body1"
derived_base_feature "Derived Base Feature2" bodies "Body1 (1)"
derived_base_feature "Derived Base Feature3" bodies "Body1 (2)"
derived_base_feature "Derived Base Feature4" bodies "Body1 (3)"
derived_base_feature "Derived Base Feature5" bodies "Body1 (4)"
derived_base_feature "Derived Base Feature6" bodies "Body1"
derived_base_feature "Derived Base Feature7" bodies "Body1"
derived_base_feature "Derived Base Feature8" bodies "Body1"
named bodies: "Body1", "Body1 (1)", "Body1 (2)", "Body1 (3)", "Body1 (4)"

design "Water Cooled Spindle Motor 1"
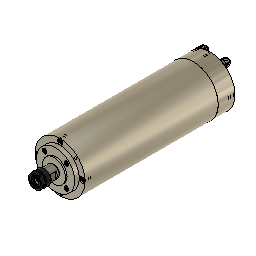
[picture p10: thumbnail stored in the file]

design "SHF_16"
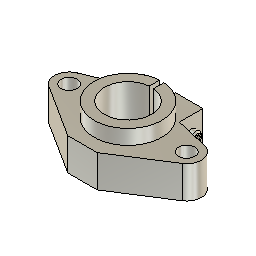
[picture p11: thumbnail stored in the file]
base_feature "Base Feature"
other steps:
create_component "CreateComponent1"

design "gora_karetki"
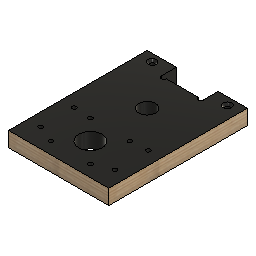
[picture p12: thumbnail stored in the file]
derived_context "$ 4cbbf0e9-ff7c-4a9b-83f7-e76befc725c5챱窴Ც똯$ a4974d71-8db2-4fde-91a5-83f0541c0199́   Ā켐畄躵酜␀ 䔀㌰㠷䔴ⵄ䔵㤱㐭ㅅⴴ㥂㉆㌭あ〷㜱㄰䌸D  czarnula_main v70     Ā¶          뼁    Ā ĀŦ   먁䡹䫷>$ ㍄㌹〷㠲䌭〲ⵃ"
derived_context "DerivedContext2"
sketch "Sketch1" plane through (14, -5, -1) normal (0, -1, 0) x axis (1, 0, 0)
  line L1 (13.6, 5.7) -> (13.6, 4.3)
  line L2 (31, -23) -> (-89, -23)
  line L3 (31, 157) -> (31, -23)
  line L4 (-89, 157) -> (31, 157)
  line L5 (-89, -23) -> (-89, 157)
  line L6 (31, 157) -> (-89, 157)
  line L7 (31, 139) -> (31, 157)
  line L8 (-89, 139) -> (31, 139)
  line L9 (-89, 157) -> (-89, 139)
  arc A1 centre (16, 5) radius 2.5 clockwise from (13.6, 5.7) to (13.6, 4.3)
  circle C1 centre (16, 95) radius 2.5
  circle C2 centre (16, 127) radius 2.5
  circle C3 centre (16, 37) radius 2.5
  circle C4 centre (-74, 81) radius 2.5
  circle C5 centre (-44, 5) radius 2.5
  circle C6 centre (-44, 95) radius 2.5
  circle C7 centre (-44, 127) radius 2.5
  circle C8 centre (-44, 37) radius 2.5
  circle C9 centre (-74, 51) radius 2.5
  point P17 (-89, 157)
  point P18 (-89, 157)
  point P19 (31, 157)
  point P21 (-89, 139)
  horizontal L6
  vertical L7
  horizontal L8
  vertical L9
  coincident P17 P18
  dimension "d1" distance P18 P19 = 120
  dimension "d2" distance P18 P21 = 18
extrude "Extrude1" new body sketch "Sketch1" profile of L3 L4 L5 L6 L7 L8 L9 along normal blind 148
sketch "Sketch2" plane through (0, 0, 156) normal (0, 0, 1) x axis (-1, 0, 0)
  line L1 (75, 5) -> (-45, 5)
  line L2 (75, 153) -> (75, 5)
  line L3 (-45, 153) -> (75, 153)
  line L4 (-45, 5) -> (-45, 153)
  circle C1 centre (15, 133) radius 14
  point P6 (15, 133)
  dimension "d5" distance L4 P6 = 60
  dimension "d6" distance L3 P6 = 20
  dimension "d7" diameter C1 = 28
extrude "Extrude2" cut sketch "Sketch2" profile of C1 against normal blind 20
sketch "Sketch4" plane through (0, 0, 156) normal (0, 0, 1) x axis (-1, 0, 0)
  line L1 (75, 5) -> (-45, 5)
  line L2 (75, 153) -> (75, 5)
  line L3 (-45, 153) -> (75, 153)
  line L4 (-45, 5) -> (-45, 153)
  line L5 (16.5446, 85.5344) -> (52.4656, 121.4554)
  line L6 (-22.4656, 121.4554) -> (13.4554, 85.5344)
  line L7 (13.4554, 160.4656) -> (-22.4656, 124.5446)
  line L8 (52.4656, 124.5446) -> (16.5446, 160.4656)
  line L9 (48.4066, 133) -> (48.4066, 123)
  line L10 (-18.4066, 133) -> (-18.4066, 123)
  line L11 (15, 99.5934) -> (15, 89.5934)
  circle C1 centre (15, 133) radius 14
  arc A1 centre (50.921, 123) radius 2.1844 clockwise from (52.4656, 124.5446) to (52.4656, 121.4554)
  arc A2 centre (15, 87.079) radius 2.1844 clockwise from (16.5446, 85.5344) to (13.4554, 85.5344)
  arc A3 centre (-20.921, 123) radius 2.1844 clockwise from (-22.4656, 121.4554) to (-22.4656, 124.5446)
  arc A4 centre (15, 158.921) radius 2.1844 clockwise from (13.4554, 160.4656) to (16.5446, 160.4656)
  circle C2 centre (15, 123) radius 20.32
  circle C3 centre (48.4066, 123) radius 2.54
  circle C4 centre (15, 89.5934) radius 2.54
  circle C5 centre (-18.4066, 123) radius 2.54
  circle C6 centre (15, 156.4066) radius 2.54
  circle C7 centre (60, 14) radius 2.5
  circle C8 centre (-30, 14) radius 2.5
  circle C9 centre (48.4066, 133) radius 2.5
  circle C10 centre (15, 99.5934) radius 2.5
  circle C11 centre (-18.4066, 133) radius 2.5
  point P20 (48.4066, 123)
  point P26 (48.4066, 123)
  point P22 (-18.4066, 123)
  point P28 (-18.4066, 123)
  point P21 (15, 89.5934)
  point P30 (15, 89.5934)
  point P27 (48.4066, 133)
  point P32 (48.4066, 133)
  point P31 (15, 99.5934)
  point P33 (15, 99.5934)
  point P29 (-18.4066, 133)
  point P34 (-18.4066, 133)
  point P24 (60, 14)
  point P25 (-30, 14)
  coincident P20 P26
  vertical L9
  coincident P22 P28
  vertical L10
  coincident P21 P30
  vertical L11
  coincident P27 P32
  coincident P31 P33
  coincident P29 P34
  dimension "d12" distance L2 P24 = 15
  dimension "d13" distance L4 P25 = 15
  dimension "d14" distance L1 P24 = 9
  dimension "d15" distance L1 P25 = 9
  dimension "d16" diameter C7 = 5
  dimension "d17" diameter C8 = 5
  dimension "d21" distance P26 P27 = 10
  dimension "d22" distance P28 P29 = 10
  dimension "d23" distance P30 P31 = 10
  dimension "d24" diameter C9 = 5
  dimension "d25" diameter C10 = 5
  dimension "d26" diameter C11 = 5
extrude "Extrude4" cut sketch "Sketch4" profile of C7 C8 against normal blind 20
chamfer "Chamfer1" distance 2.5
sketch "Sketch5" plane through (0, -5, 0) normal (0, 1, 0) x axis (-1, 0, 0)
  line L1 (75, 138) -> (-45, 138)
  line L2 (75, 156) -> (75, 138)
  line L3 (-45, 156) -> (75, 156)
  line L4 (-45, 138) -> (-45, 156)
  line L5 (75, 147) -> (-45, 147)
  line L6 (15, 138) -> (15, 156)
  line L7 (40, 156) -> (-10, 156)
  line L8 (40, 138) -> (40, 156)
  line L9 (-10, 138) -> (40, 138)
  line L10 (-10, 156) -> (-10, 138)
  line L11 (40, 138) -> (-10, 156)
  line L12 (-10, 138) -> (40, 156)
  point P6 (-45, 147)
  point P7 (75, 147)
  point P8 (15, 156)
  point P9 (15, 138)
  point P14 (15, 147)
  point P3 (75, 138)
  point P12 (40, 138)
  point P13 (-10, 138)
  midpoint L4 P6
  midpoint L2 P7
  midpoint L3 P8
  midpoint L1 P9
  horizontal L7
  perpendicular L7 L8
  parallel L7 L9
  parallel L8 L10
  coincident L11 P14
  coincident L12 P14
  midpoint L5 P14
  coincident P3 L9
  dimension "d27" distance P12 P13 = 50
extrude "Extrude5" cut sketch "Sketch5" profile of L1 L3 L7 L8 L9 L10 against normal blind 18
sketch "Sketch6" plane through (0, 0, 156) normal (0, 0, 1) x axis (-1, 0, 0)
  line L1 (40, 5) -> (40, 23)
  line L2 (75, 5) -> (40, 5)
  line L3 (75, 153) -> (75, 5)
  line L4 (-45, 153) -> (75, 153)
  line L5 (-45, 5) -> (-45, 153)
  line L6 (-10, 5) -> (-45, 5)
  line L7 (-10, 23) -> (-10, 5)
  line L8 (40, 23) -> (-10, 23)
  circle C1 centre (60, 14) radius 5
  circle C2 centre (15, 133) radius 14
  circle C3 centre (-30, 14) radius 5
  circle C4 centre (-7, 23) radius 3
  circle C5 centre (37, 23) radius 3
  point P13 (-7, 23)
  point P14 (37, 23)
  coincident L8 P13
  coincident L8 P14
  dimension "d30" diameter C4 = 6
  dimension "d31" diameter C5 = 6
  dimension "d32" distance L7 P13 = 3
  dimension "d33" distance L1 P14 = 3
extrude "Extrude6" cut sketch "Sketch6" profile of L8 C1 C4 C5 against normal blind 18
extrude "Extrude7" add of existing geometry blind 18
sketch "Sketch7" plane through (0, 0, 156) normal (0, 0, 1) x axis (-1, 0, 0)
  line L1 (34, 23) -> (-4, 23)
  line L2 (40, 5) -> (40, 23)
  line L3 (75, 5) -> (40, 5)
  line L4 (75, 171) -> (75, 5)
  line L5 (-45, 171) -> (75, 171)
  line L6 (-45, 5) -> (-45, 171)
  line L7 (-10, 5) -> (-45, 5)
  line L8 (-10, 23) -> (-10, 5)
  arc A1 centre (-7, 23) radius 3 clockwise from (-10, 23) to (-4, 23)
  arc A2 centre (37, 23) radius 3 clockwise from (34, 23) to (40, 23)
  circle C1 centre (60, 14) radius 5
  circle C2 centre (15, 133) radius 14
  circle C3 centre (-30, 14) radius 5
  circle C4 centre (-18.4066, 133) radius 2.5
  circle C5 centre (-8.622, 109.378) radius 2.5
  circle C6 centre (15, 99.5934) radius 2.5
  circle C7 centre (38.622, 109.378) radius 2.5
  circle C8 centre (48.4066, 133) radius 2.5
  circle C9 centre (38.622, 156.622) radius 2.5
  circle C10 centre (15, 166.4066) radius 2.5
  circle C11 centre (-8.622, 156.622) radius 2.5
  dimension "d39" C-Pattern1-Angle = 360
extrude "Extrude8" cut sketch "Sketch7" profile of C5 C7 C9 C11 against normal blind 19
sketch "Sketch8" plane through (0, 0, 156) normal (0, 0, 1) x axis (-1, 0, 0)
  line L1 (34, 23) -> (-4, 23)
  line L2 (40, 5) -> (40, 23)
  line L3 (75, 5) -> (40, 5)
  line L4 (75, 171) -> (75, 5)
  line L5 (-45, 171) -> (75, 171)
  line L6 (-45, 5) -> (-45, 171)
  line L7 (-10, 5) -> (-45, 5)
  line L8 (-10, 23) -> (-10, 5)
  line L9 (15, 23) -> (15, 171)
  circle C1 centre (38.622, 109.378) radius 2.5
  circle C2 centre (-8.622, 109.378) radius 2.5
  circle C3 centre (38.622, 156.622) radius 2.5
  circle C4 centre (-8.622, 156.622) radius 2.5
  arc A1 centre (-7, 23) radius 3 clockwise from (-10, 23) to (-4, 23)
  arc A2 centre (37, 23) radius 3 clockwise from (34, 23) to (40, 23)
  circle C5 centre (60, 14) radius 5
  circle C6 centre (15, 133) radius 14
  circle C7 centre (-30, 14) radius 5
  circle C8 centre (59.5, 108) radius 2.5
  circle C9 centre (59.5, 148) radius 2.5
  circle C10 centre (-29.5, 108) radius 2.5
  circle C11 centre (-29.5, 148) radius 2.5
  circle C12 centre (15, 65) radius 10
  point P23 (15, 171)
  point P24 (15, 23)
  point P21 (59.5, 108)
  point P22 (59.5, 148)
  point P27 (15, 65)
  midpoint L5 P23
  midpoint L1 P24
  symmetric C8 L9 C10
  symmetric C9 L9 C11
  vertical P21 P22
  coincident L9 P27
  dimension "d42" diameter C9 = 5
  dimension "d43" diameter C8 = 5
  dimension "d44" distance P21 P22 = 40
  dimension "d45" distance L3 P21 = 103
  dimension "d48" distance L4 P22 = 15.5
  dimension "d49" diameter C12 = 20
extrude "Extrude9" cut sketch "Sketch8" profile of C8 C9 C10 C11 against normal blind 20
extrude "Extrude10" cut sketch "Sketch8" profile of C12 against normal blind 20
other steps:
derived_base_feature "Derived Base Feature1" bodies "Body1"
derived_base_feature "Derived Base Feature2" bodies "Body1"
named bodies: "Body1"

design "bok_zetki"
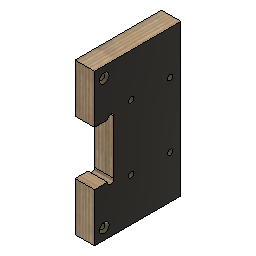
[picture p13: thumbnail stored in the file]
derived_context "$ 01a98ca4-6276-4cb7-86b7-8fa34e8b930d캭鿷텞스$ a4974d71-8db2-4fde-91a5-83f0541c0199́   Ā镵減죁Ⱈ␀ 䔀㌰㠷䔴ⵄ䔵㤱㐭ㅅⴴ㥂㉆㌭あ〷㜱㄰䌸D  czarnula_main v52     Ā¶          쀁    Ā Āà   封漭쟠鐜®$ ㍄㌹〷㠲䌭〲ⵃ"
sketch "Sketch1" plane through (48.7406, 0, 0) normal (1, 0, 0) x axis (0, 1, 0)
  line L1 (-118.512, 82.3182) -> (-118.512, -0.1818)
  line L2 (-130.762, 82.3182) -> (-118.512, 82.3182)
  line L3 (-130.762, -0.1818) -> (-130.762, 82.3182)
  line L4 (-118.512, -0.1818) -> (-130.762, -0.1818)
  line L5 (0, 140) -> (-80, 140)
  line L6 (0, 0) -> (0, 140)
  line L7 (-80, 0) -> (0, 0)
  line L8 (-80, 140) -> (-80, 0)
  circle C1 centre (-125.012, 11.0682) radius 2.5
  circle C2 centre (-125.012, 71.0682) radius 2.5
  circle C3 centre (-10, 100) radius 2.5
  circle C4 centre (-46, 100) radius 2.5
  circle C5 centre (-46, 40) radius 2.5
  circle C6 centre (-10, 40) radius 2.5
  circle C7 centre (-71, 130) radius 2.5
  circle C8 centre (-71, 10) radius 2.5
  circle C9 centre (-71, 70) radius 2.5
  point P12 (-10, 100)
  point P15 (-10, 40)
  point P13 (-46, 100)
  point P14 (-46, 40)
  point P1 (0, 0)
  point P10 (0, 0)
  point P8 (-80, 140)
  point P9 (0, 140)
  point P11 (-80, 0)
  point P16 (-71, 130)
  point P17 (-71, 10)
  point P18 (-71, 70)
  horizontal L5
  vertical L6
  horizontal L7
  vertical L8
  vertical P12 P15
  horizontal P12 P13
  horizontal P14 P15
  coincident P1 P10
  dimension "d1" distance P8 P9 = 80
  dimension "d2" distance P8 P11 = 140
  dimension "d3" diameter C3 = 5
  dimension "d4" diameter C4 = 5 (= "d3")
  dimension "d5" diameter C5 = 5 (= "d3")
  dimension "d6" diameter C6 = 5
  dimension "d7" distance L6 P12 = 10
  dimension "d8" distance P12 P15 = 60
  dimension "d9" distance L5 P12 = 40
  dimension "d12" diameter C7 = 5
  dimension "d13" distance L8 P16 = 9
  dimension "d14" distance L5 P16 = 10
  dimension "d15" distance P12 P13 = 36
  dimension "d16" distance P14 P15 = 36
  dimension "d17" diameter C8 = 5
  dimension "d18" distance L7 P17 = 10
  dimension "d19" distance L8 P17 = 9
  dimension "d20" diameter C9 = 5
  dimension "d21" distance L8 P18 = 9
  dimension "d22" distance L5 P18 = 70
extrude "Extrude1" new body sketch "Sketch1" profile of L5 L6 L7 L8 C3 C4 C5 C6 C7 C8 C9 along normal blind 18
chamfer "Chamfer1" distance 2
sketch "Szkic2" plane through (0, -80, 0) normal (0, -1, 0) x axis (1, 0, 0)
  line L1 (48.7406, 0) -> (48.7406, 140)
  line L2 (66.7406, 0) -> (48.7406, 0)
  line L3 (66.7406, 140) -> (66.7406, 0)
  line L4 (48.7406, 140) -> (66.7406, 140)
  line L5 (57.7406, 0) -> (57.7406, 140)
  line L6 (66.7406, 70) -> (48.7406, 70)
  line L7 (66.7406, 45) -> (48.7406, 45)
  line L8 (66.7406, 95) -> (66.7406, 45)
  line L9 (48.7406, 95) -> (66.7406, 95)
  line L10 (48.7406, 45) -> (48.7406, 95)
  line L11 (66.7406, 95) -> (48.7406, 45)
  line L12 (48.7406, 95) -> (66.7406, 45)
  point P6 (57.7406, 140)
  point P7 (57.7406, 0)
  point P8 (48.7406, 70)
  point P9 (66.7406, 70)
  point P14 (57.7406, 70)
  point P12 (66.7406, 95)
  point P13 (48.7406, 95)
  point P11 (66.7406, 45)
  midpoint L4 P6
  midpoint L2 P7
  midpoint L1 P8
  midpoint L3 P9
  horizontal L7
  perpendicular L7 L8
  parallel L7 L9
  parallel L8 L10
  coincident L11 P14
  coincident L12 P14
  midpoint L6 P14
  dimension "d24" distance P12 P13 = 18
  dimension "d25" distance P11 P12 = 50
extrude "Wyciągnięcie proste2" cut sketch "Szkic2" profile of L1 L3 L7 L8 L9 L10 against normal blind 18
sketch "Szkic3" plane through (66.7406, 0, 0) normal (1, 0, 0) x axis (0, 1, 0)
  line L1 (-62, 95) -> (-80, 95)
  line L2 (-62, 45) -> (-62, 95)
  line L3 (-80, 45) -> (-62, 45)
  line L4 (-80, 0) -> (-80, 45)
  line L5 (0, 0) -> (-80, 0)
  line L6 (0, 140) -> (0, 0)
  line L7 (-80, 140) -> (0, 140)
  line L8 (-80, 95) -> (-80, 140)
  circle C1 centre (-71, 10) radius 4.5
  circle C2 centre (-71, 130) radius 4.5
  circle C3 centre (-46, 40) radius 2.5
  circle C4 centre (-10, 100) radius 2.5
  circle C5 centre (-46, 100) radius 2.5
  circle C6 centre (-10, 40) radius 2.5
  circle C7 centre (-65, 45) radius 3
  circle C8 centre (-65, 95) radius 3
  point P16 (-65, 45)
  point P17 (-65, 95)
  coincident L3 P16
  coincident L1 P17
  dimension "d28" diameter C7 = 6
  dimension "d29" diameter C8 = 6
  dimension "d30" distance L2 P17 = 3
  dimension "d31" distance L2 P16 = 3
extrude "Wyciągnięcie proste3" cut sketch "Szkic3" profile of L1 L3 C7 C8 against normal blind 20
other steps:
derived_base_feature "Derived Base Feature" bodies "Body1"
named bodies: "Body1"

design "stopka"
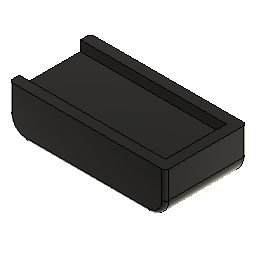
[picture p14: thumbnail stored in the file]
derived_context "$ f32d2d59-8845-4d75-80c6-16edb82da0e3ꉼ줆ᒔ揄$ a4974d71-8db2-4fde-91a5-83f0541c0199́   Ā뛲踍륑␀ 䔀㌰㠷䔴ⵄ䔵㤱㐭ㅅⴴ㥂㉆㌭あ〷㜱㄰䌸D  czarnula_main v50     Ā¶          뼁    Ā Āȹ    ᐛ셤ⴡÐ$ ㍄㌹〷㠲䌭〲ⵃ"
sketch "Sketch1" plane through (0, 0, -223.4) normal (0, 0, -1) x axis (1, 0, 0)
  line L1 (-270, 360.5) -> (270, 360.5)
  line L2 (-270, 342.5) -> (-270, 360.5)
  line L3 (270, 342.5) -> (-270, 342.5)
  line L4 (270, 360.5) -> (270, 342.5)
  line L5 (230, 360.5) -> (270, 360.5)
  line L6 (230, 342.5) -> (230, 360.5)
  line L7 (270, 342.5) -> (230, 342.5)
  line L8 (270, 360.5) -> (270, 342.5)
  line L9 (273, 339.5) -> (227, 339.5)
  line L10 (273, 363.5) -> (273, 339.5)
  line L11 (227, 363.5) -> (273, 363.5)
  line L12 (227, 339.5) -> (227, 363.5)
  line L13 (227, 360.5) -> (230, 360.5)
  line L14 (227, 342.5) -> (230, 342.5)
  point P2 (270, 360.5)
  point P6 (270, 360.5)
  point P14 (227, 360.5)
  point P15 (227, 342.5)
  point P7 (230, 360.5)
  point P9 (270, 342.5)
  horizontal L5
  vertical L6
  horizontal L7
  vertical L8
  coincident P2 P6
  coincident L1 P14
  coincident L12 P14
  coincident L12 P15
  coincident L3 P15
  dimension "d1" distance P6 P7 = 40
  dimension "d2" distance P6 P9 = 18
  dimension "d3" = 3
extrude "Extrude1" new body sketch "Sketch1" profile of L1 L3 L4 L5 L6 L7 L8 L12 L9 L10 L11 along normal blind 10
extrude "Extrude2" add sketch "Sketch1" profile of L1 L3 L4 L5 L7 L8 L12 L9 L10 L11 L13 L14 against normal blind 3
fillet "Fillet1" radius 5
fillet "Fillet2" radius 1
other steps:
derived_base_feature "Derived Base Feature" bodies "Body1"
named bodies: "Body1"

design "SA16_500mm"
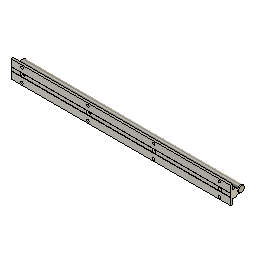
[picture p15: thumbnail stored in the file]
base_feature "Base Feature"
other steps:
create_component "CreateComponent2"

design "nasadki_boczne"
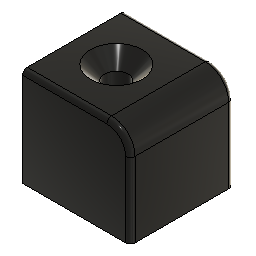
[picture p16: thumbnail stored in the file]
derived_context "$ 9ac93874-62b2-4764-a03c-3aea9039c19bস艄ጥ޹$ a4974d71-8db2-4fde-91a5-83f0541c0199́   Āꠙ珶鐑졨␀ 䔀㌰㠷䔴ⵄ䔵㤱㐭ㅅⴴ㥂㉆㌭あ〷㜱㄰䌸D  czarnula_main v31     Ā¶          뼁    Ā Āȹ    ᐛ셤ⴡÐ$ ㍄㌹〷㠲䌭〲ⵃ"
